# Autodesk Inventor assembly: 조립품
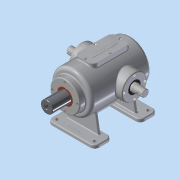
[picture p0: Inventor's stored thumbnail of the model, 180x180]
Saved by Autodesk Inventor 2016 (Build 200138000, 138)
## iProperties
Created: 2018-11
Part Number: 조립품
Material: 일반
Document SubType Name: Assembly
Designer: user
Mass: 8191.27 g
Surface Area: 4241.81 cm^2
Volume: 1855.49 cm^3
Density: 4.41462 g/cm^3
Author: user
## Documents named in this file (15)
- C:\Users\user\Desktop\381121V1007\조립품.iam
- C:\Users\user\Desktop\381121V1007\가변스프링.ipt
- C:\Users\user\Desktop\381121V1007\베어링 6205.ipt
- 베어링 6205.ipt
- C:\Users\user\Desktop\381121V1007\본체.ipt
- C:\Users\user\Desktop\381121V1007\볼트 M4x0.7.ipt
- C:\Users\user\Desktop\381121V1007\부시.ipt
- C:\Users\user\Desktop\381121V1007\상부커버.ipt
- C:\Users\user\Desktop\381121V1007\슬라이드 커버.ipt
- C:\Users\user\Desktop\381121V1007\슬라이드.ipt
- C:\Users\user\Desktop\381121V1007\오일실.ipt
- 오일실.ipt
- C:\Users\user\Desktop\381121V1007\육각머리볼트 M4.ipt
- C:\Users\user\Desktop\381121V1007\축 커버.ipt
- C:\Users\user\Desktop\381121V1007\편심축.ipt
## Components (13 placed, 2 different names)
1. 가변스프링:1
2. M4x0.7:1
3. M4x0.7:4
4. M4x0.7:5
5. M4x0.7:6
6. M4x0.7:3
7. M4x0.7:7
8. M4x0.7:8
9. M4x0.7:9
10. M4x0.7:2
11. M4x0.7:10
12. M4x0.7:11
13. M4x0.7:12
